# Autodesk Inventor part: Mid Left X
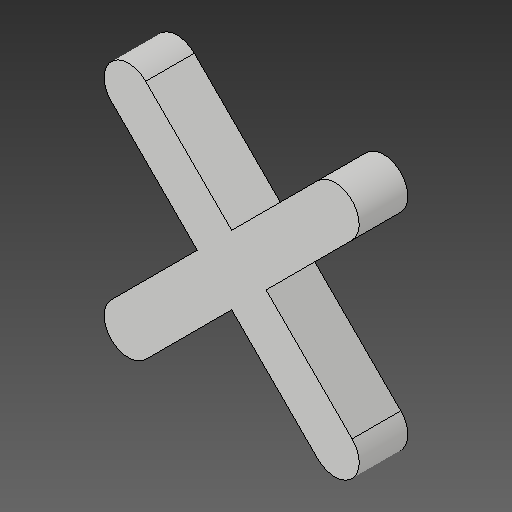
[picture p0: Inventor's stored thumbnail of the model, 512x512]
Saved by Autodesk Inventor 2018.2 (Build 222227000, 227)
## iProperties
Created: 2018-03
Part Number: Mid Left X
Material: Generic
Document SubType Name: Modeling
Designer: PeterMaxwell-Stewart
Mass: 1.57135 g
Surface Area: 12.8562 cm^2
Volume: 1.57135 cm^3
Density: 1 g/cm^3
Appearance: Default
Author: PeterMaxwell-Stewart
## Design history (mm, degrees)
derived "O's and X's.ipt"
feature "Mid Left X::O's and X's.ipt" dims "d0" = 10
tag "TaggingFeature1"
body "Solid1"
